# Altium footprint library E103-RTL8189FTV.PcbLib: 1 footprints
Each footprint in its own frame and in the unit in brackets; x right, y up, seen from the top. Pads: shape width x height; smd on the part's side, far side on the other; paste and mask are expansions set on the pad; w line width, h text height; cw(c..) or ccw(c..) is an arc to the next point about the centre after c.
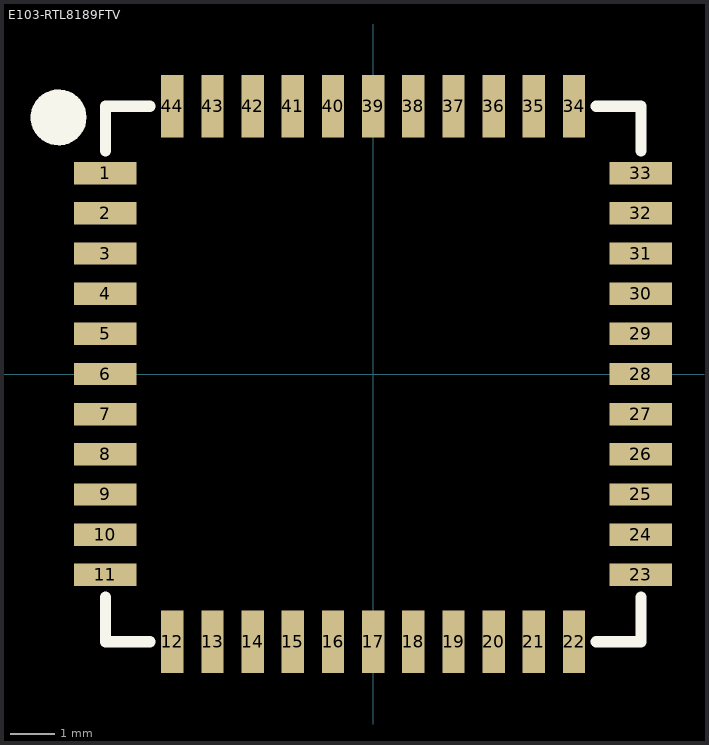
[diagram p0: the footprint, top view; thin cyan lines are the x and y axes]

## E103-RTL8189FTV [mm]
pads (44):
  rect 1.4x0.5 smd mask+0: 1(-6,4.5) 2(-6,3.6) 3(-6,2.7) 4(-6,1.8) 5(-6,0.9) 6(-6,0) 7(-6,-0.9) 8(-6,-1.8) 9(-6,-2.7) 10(-6,-3.6) 11(-6,-4.5) 23(6,-4.5) 24(6,-3.6) 25(6,-2.7) 26(6,-1.8) 27(6,-0.9) 28(6,0) 29(6,0.9) 30(6,1.8) 31(6,2.7) 32(6,3.6) 33(6,4.5)
  rect 0.5x1.4 smd mask+0: 12(-4.5,-6) 13(-3.6,-6) 14(-2.7,-6) 15(-1.8,-6) 16(-0.9,-6) 17(0,-6) 18(0.9,-6) 19(1.8,-6) 20(2.7,-6) 21(3.6,-6) 22(4.5,-6) 34(4.5,6) 35(3.6,6) 36(2.7,6) 37(1.8,6) 38(0.9,6) 39(0,6) 40(-0.9,6) 41(-1.8,6) 42(-2.7,6) 43(-3.6,6) 44(-4.5,6)
Top Overlay:
  circle w0.254: c-7.05,5.75 r0.5
  region: -6.855,6.221 -6.69,6.11 -6.579,5.945 -6.54,5.75 -6.579,5.555 -6.69,5.39 -6.855,5.279 -7.05,5.24 -7.245,5.279 -7.41,5.39 -7.521,5.555 -7.56,5.75 -7.521,5.945 -7.41,6.11 -7.245,6.221 -7.05,6.26
  lines w0.254: -6,-5 -6,-6 -5,-6 ; -6,5 -6,6 -5,6 ; 5,-6 6,-6 6,-5 ; 5,6 6,6 6,5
